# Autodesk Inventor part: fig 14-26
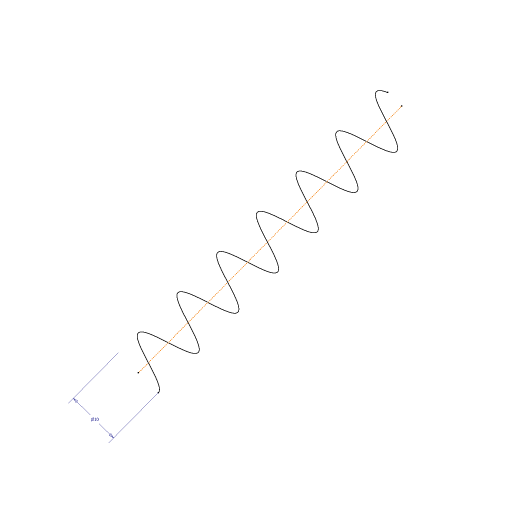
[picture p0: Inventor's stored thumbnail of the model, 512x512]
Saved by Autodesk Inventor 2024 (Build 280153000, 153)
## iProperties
Created: 2007-03
Part Number: fig 14-26
Document SubType Name: Modeling
Designer: Administrator
Density: 1 g/cm^3
Material: Generic
Appearance: Default
Author: Administrator
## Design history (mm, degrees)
sketch "3D Sketch1"
  node "Helical Curve2" dims "d4" = 10, "d6" = 10, "d7" = 0
node "Sketch1"
other parameters: "d5" = 66.31
